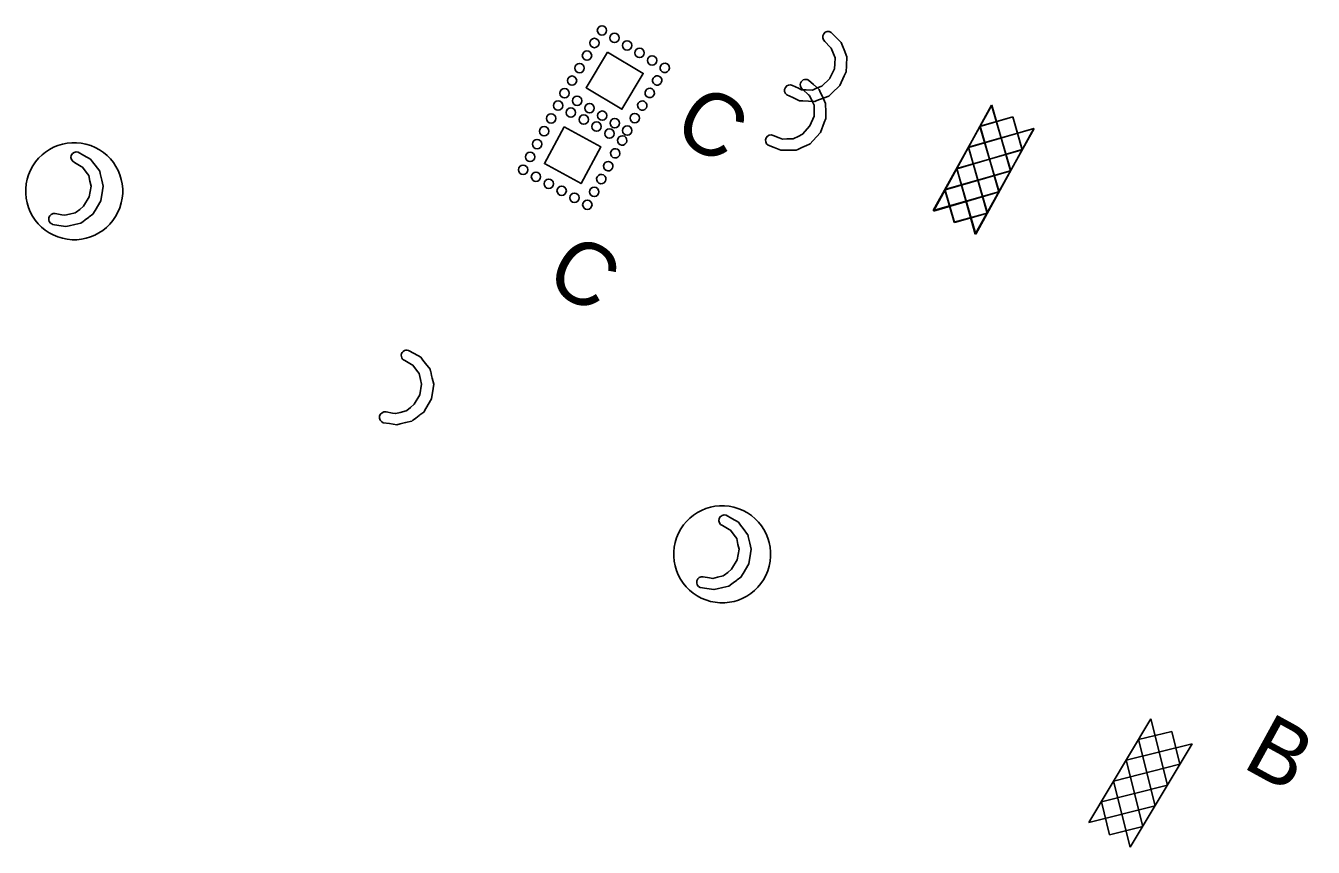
# Model space of a CAD drawing. Extents: x 2283629 to 2286552, y 529718 to 531440.
# Drawn here: x 2284496.6 to 2284805.1, y 530384.9 to 530581.6 of the extents above; entities that cross this region are included whole.
import ezdxf

# ---------------------------------------------------------------- set-up
doc = ezdxf.new("R2010")
doc.units = 0
for name, color, linetype in [('Draft_Corridor_Graphics_Final', 7, 'Continuous'), ('P_NCDOT_Terrain_Exterior', 7, 'Continuous'), ('P_NCDOT_Terrain_Model_Triangles', 7, 'Continuous'), ('P_NCDOT_Terrain_Triangle_Vertices', 7, 'Continuous'), ('P_NCDOT_Terrain_Void', 7, 'Continuous'), ('P_RDY_TC_Pvmt_Asphalt_Base_Course_Wedge', 7, 'Continuous'), ('P_RDY_TC_Pvmt_Asphalt_Intermediate_Course', 7, 'Continuous'), ('P_RDY_TC_Pvmt_Asphalt_Surface_Course', 7, 'Continuous'), ('P_RDY_TL_Paved_Shoulder_Sub', 7, 'Continuous'), ('P_RDY_TL_Sidewalk', 7, 'Continuous')]:
    doc.layers.add(name, color=color, linetype=linetype)

msp = doc.modelspace()

# ---------------------------------------------------------------- linework, layer by layer
at = {"layer": 'Draft_Corridor_Graphics_Final'}
for p, q in [((2284684.14, 530565.09), (2284684.38, 530564.86)), ((2284684.47, 530557.6), (2284684.46, 530557.59)), ((2284680.63, 530554.62), (2284680.41, 530554.52)), ((2284682.69, 530555.63), (2284681.62, 530555.11))]:
    msp.add_line(p, q, dxfattribs=at)
for points in [[(2284674.45, 530552.98), (2284675.89, 530552.42), (2284677.53, 530551.79), (2284678.34, 530551.8), (2284679.69, 530551.81), (2284681.2, 530551.83), (2284681.2, 530551.83), (2284681.54, 530551.99), (2284681.69, 530552.06), (2284682.36, 530552.36), (2284683.23, 530552.75), (2284683.45, 530552.85), (2284684.48, 530553.32), (2284685.18, 530554.07), (2284686.98, 530556.01), (2284686.98, 530556.02), (2284687.91, 530558.39), (2284688.29, 530559.36), (2284688.26, 530560.83), (2284688.25, 530561.49), (2284688.23, 530562.45), (2284688.23, 530562.53), (2284688.22, 530562.97), (2284688.22, 530563.01), (2284687.45, 530564.63), (2284687.02, 530565.54), (2284686.66, 530566.3), (2284685.31, 530567.51), (2284684.15, 530568.56)], [(2284682.77, 530566.36), (2284684.14, 530565.09), (2284684.38, 530564.86), (2284685.01, 530563.52), (2284685.45, 530562.59), (2284685.44, 530561.15), (2284685.44, 530559.94), (2284684.47, 530557.6), (2284684.46, 530557.59), (2284682.69, 530555.63), (2284681.62, 530555.11), (2284680.63, 530554.62), (2284680.41, 530554.52), (2284678.96, 530554.49), (2284677.86, 530554.46), (2284677.13, 530554.75), (2284675.68, 530555.33), (2284675.68, 530555.33)]]:
    msp.add_lwpolyline(points, dxfattribs=at)
for centre, radius, start in [((2284683.46, 530567.46), 1.3, 57.9198), ((2284675.16, 530554.11), 1.33, 66.8072)]:
    msp.add_arc(centre, radius, start, 237.9198, dxfattribs=at)
at = {"layer": 'P_NCDOT_Terrain_Exterior'}
for p, q in [((2284766.16, 530415.58), (2284751.29, 530390.79)), ((2284770.12, 530399.73), (2284766.16, 530415.58)), ((2284763.2, 530410.64), (2284771.14, 530412.6)), ((2284773.09, 530404.77), (2284771.14, 530412.6)), ((2284760.22, 530405.67), (2284776.06, 530409.64)), ((2284776.06, 530409.64), (2284761.2, 530384.85)), ((2284767.14, 530394.76), (2284763.2, 530410.64)), ((2284764.19, 530389.82), (2284760.22, 530405.67)), ((2284757.23, 530400.7), (2284773.1, 530404.71)), ((2284754.28, 530395.76), (2284770.12, 530399.73)), ((2284761.2, 530384.85), (2284757.23, 530400.7)), ((2284751.29, 530390.79), (2284767.14, 530394.76)), ((2284756.26, 530387.8), (2284754.28, 530395.76)), ((2284756.26, 530387.8), (2284764.19, 530389.82))]:
    msp.add_line(p, q, dxfattribs=at)
at = {"layer": 'P_NCDOT_Terrain_Model_Triangles'}
for p, q in [((2284689.35, 530576.51), (2284689.58, 530576.27)), ((2284685.2, 530566.29), (2284684.98, 530566.2)), ((2284687.32, 530567.17), (2284686.22, 530566.71)), ((2284689.21, 530569.01), (2284689.21, 530569))]:
    msp.add_line(p, q, dxfattribs=at)
for points in [[(2284678.93, 530565.03), (2284680.34, 530564.38), (2284681.93, 530563.65), (2284682.74, 530563.61), (2284684.08, 530563.54), (2284685.59, 530563.46), (2284685.6, 530563.47), (2284685.94, 530563.6), (2284686.1, 530563.66), (2284686.79, 530563.92), (2284687.68, 530564.26), (2284687.91, 530564.34), (2284688.96, 530564.75), (2284689.71, 530565.46), (2284691.62, 530567.27), (2284691.63, 530567.28), (2284692.7, 530569.59), (2284693.14, 530570.54), (2284693.2, 530572), (2284693.23, 530572.67), (2284693.27, 530573.62), (2284693.28, 530573.7), (2284693.29, 530574.14), (2284693.3, 530574.18), (2284692.63, 530575.85), (2284692.26, 530576.79), (2284691.94, 530577.56), (2284690.67, 530578.86), (2284689.58, 530579.97)], [(2284688.07, 530577.86), (2284689.35, 530576.51), (2284689.58, 530576.27), (2284690.12, 530574.9), (2284690.5, 530573.94), (2284690.41, 530572.5), (2284690.33, 530571.3), (2284689.21, 530569.01), (2284689.21, 530569), (2284687.32, 530567.17), (2284686.22, 530566.71), (2284685.2, 530566.29), (2284684.98, 530566.2), (2284683.53, 530566.25), (2284682.43, 530566.29), (2284681.71, 530566.63), (2284680.31, 530567.3), (2284680.31, 530567.3)]]:
    msp.add_lwpolyline(points, dxfattribs=at)
for centre, radius, start in [((2284688.82, 530578.92), 1.3, 54.3604), ((2284679.71, 530566.11), 1.33, 63.2478)]:
    msp.add_arc(centre, radius, start, 234.3604, dxfattribs=at)
at = {"layer": 'P_NCDOT_Terrain_Triangle_Vertices'}
for p, q in [((2284509.87, 530547.92), (2284508.27, 530548.87)), ((2284509.87, 530547.92), (2284510.15, 530547.75)), ((2284511.05, 530546.57), (2284510.15, 530547.75)), ((2284511.67, 530545.75), (2284511.05, 530546.57)), ((2284511.97, 530544.34), (2284511.67, 530545.75)), ((2284511.77, 530540.66), (2284512.22, 530543.16)), ((2284512.22, 530543.16), (2284511.97, 530544.34)), ((2284510.45, 530538.37), (2284509.52, 530537.63)), ((2284510.45, 530538.37), (2284511.77, 530540.65)), ((2284511.77, 530540.66), (2284511.77, 530540.65)), ((2284503.67, 530536.6), (2284505.2, 530536.33)), ((2284505.2, 530536.33), (2284505.98, 530536.2)), ((2284505.98, 530536.2), (2284507.05, 530536.46)), ((2284507.05, 530536.46), (2284508.46, 530536.8)), ((2284508.64, 530536.95), (2284508.46, 530536.8)), ((2284508.64, 530536.95), (2284509.52, 530537.63)), ((2284665.11, 530460.96), (2284663.51, 530461.91)), ((2284665.11, 530460.96), (2284665.4, 530460.79)), ((2284666.29, 530459.62), (2284665.4, 530460.79)), ((2284666.92, 530458.8), (2284666.29, 530459.62)), ((2284667.22, 530457.39), (2284666.92, 530458.8)), ((2284667.01, 530453.71), (2284667.47, 530456.21)), ((2284667.47, 530456.21), (2284667.22, 530457.39)), ((2284665.7, 530451.42), (2284667.01, 530453.7)), ((2284667.01, 530453.71), (2284667.01, 530453.7)), ((2284658.91, 530449.64), (2284660.44, 530449.38)), ((2284660.44, 530449.38), (2284661.22, 530449.25)), ((2284661.22, 530449.25), (2284662.29, 530449.51)), ((2284662.29, 530449.51), (2284663.7, 530449.85)), ((2284663.89, 530449.99), (2284663.7, 530449.85)), ((2284663.89, 530449.99), (2284664.76, 530450.68)), ((2284665.7, 530451.42), (2284664.76, 530450.68))]:
    msp.add_line(p, q, dxfattribs=at)
for points in [[(2284509.15, 530551.31), (2284510.5, 530550.53), (2284512.08, 530549.63), (2284512.59, 530548.97), (2284513.2, 530548.17), (2284514.3, 530546.75), (2284514.31, 530546.71), (2284514.41, 530546.28), (2284514.43, 530546.2), (2284514.65, 530545.27), (2284514.8, 530544.62), (2284515.13, 530543.2), (2284514.97, 530542.17), (2284514.56, 530539.65), (2284514.56, 530539.64), (2284513.21, 530537.37), (2284512.69, 530536.49), (2284511.78, 530535.81), (2284511.59, 530535.67), (2284510.82, 530535.1), (2284510.23, 530534.66), (2284510.09, 530534.56), (2284509.8, 530534.34), (2284509.79, 530534.34), (2284508.32, 530534), (2284507.01, 530533.7), (2284506.22, 530533.52), (2284504.48, 530533.79), (2284502.96, 530534.03)], [(2284664.39, 530464.35), (2284665.75, 530463.58), (2284667.32, 530462.68), (2284667.83, 530462.02), (2284668.45, 530461.21), (2284669.54, 530459.79), (2284669.55, 530459.75), (2284669.65, 530459.32), (2284669.67, 530459.25), (2284669.89, 530458.32), (2284670.04, 530457.67), (2284670.38, 530456.24), (2284670.21, 530455.21), (2284669.81, 530452.7), (2284669.8, 530452.69), (2284668.46, 530450.42), (2284667.93, 530449.53), (2284667.02, 530448.86), (2284666.83, 530448.72), (2284666.06, 530448.14), (2284665.47, 530447.71), (2284665.34, 530447.61), (2284665.04, 530447.39), (2284665.03, 530447.38), (2284663.56, 530447.05), (2284662.25, 530446.75), (2284661.46, 530446.57), (2284659.73, 530446.84), (2284658.2, 530447.08)]]:
    msp.add_lwpolyline(points, dxfattribs=at)
for centre, radius, start, end in [((2284508.2, 530541.97), 11.62, 70.1109, 160.1109), ((2284508.71, 530550.09), 1.3, 70.1109, 250.1109), ((2284508.2, 530541.97), 11.62, 340.1109, 70.1109), ((2284508.2, 530541.97), 11.62, 160.1109, 250.1109), ((2284503.41, 530535.29), 1.33, 78.9982, 250.1109), ((2284508.2, 530541.97), 11.62, 250.1109, 340.1109), ((2284663.44, 530455.01), 11.62, 70.1109, 160.1109), ((2284663.95, 530463.13), 1.3, 70.1109, 250.1109), ((2284663.44, 530455.01), 11.62, 340.1109, 70.1109), ((2284663.44, 530455.01), 11.62, 160.1109, 250.1109), ((2284658.65, 530448.33), 1.33, 78.9982, 250.1109), ((2284663.44, 530455.01), 11.62, 250.1109, 340.1109)]:
    msp.add_arc(centre, radius, start, end, dxfattribs=at)
at = {"layer": 'P_NCDOT_Terrain_Void'}
for p, q in [((2284714, 530537.34), (2284728.07, 530562.58)), ((2284728.07, 530562.58), (2284732.53, 530546.87)), ((2284738.16, 530556.96), (2284722.45, 530552.49)), ((2284724.09, 530531.72), (2284738.16, 530556.96)), ((2284733.1, 530559.79), (2284725.24, 530557.52)), ((2284725.24, 530557.52), (2284729.71, 530541.8)), ((2284733.1, 530559.79), (2284735.33, 530551.89)), ((2284735.33, 530551.89), (2284719.62, 530547.43)), ((2284722.45, 530552.49), (2284726.89, 530536.74)), ((2284732.53, 530546.87), (2284716.8, 530542.36)), ((2284719.62, 530547.43), (2284724.09, 530531.72)), ((2284729.71, 530541.8), (2284714, 530537.34)), ((2284716.82, 530542.29), (2284719.01, 530534.53)), ((2284726.89, 530536.74), (2284719.01, 530534.53))]:
    msp.add_line(p, q, dxfattribs=at)
at = {"layer": 'P_RDY_TC_Pvmt_Asphalt_Base_Course_Wedge'}
for p, q in [((2284589.03, 530500.47), (2284589.32, 530500.3)), ((2284590.98, 530493.22), (2284590.98, 530493.21)), ((2284587.88, 530489.49), (2284587.7, 530489.34)), ((2284589.68, 530490.93), (2284588.75, 530490.18))]:
    msp.add_line(p, q, dxfattribs=at)
for points in [[(2284582.21, 530486.53), (2284583.75, 530486.31), (2284585.48, 530486.05), (2284586.27, 530486.23), (2284587.58, 530486.54), (2284589.05, 530486.89), (2284589.06, 530486.89), (2284589.35, 530487.11), (2284589.49, 530487.22), (2284590.07, 530487.65), (2284590.84, 530488.23), (2284591.03, 530488.38), (2284591.93, 530489.06), (2284592.45, 530489.95), (2284593.78, 530492.22), (2284593.78, 530492.23), (2284594.17, 530494.75), (2284594.33, 530495.78), (2284593.98, 530497.21), (2284593.83, 530497.85), (2284593.6, 530498.78), (2284593.58, 530498.86), (2284593.48, 530499.29), (2284593.47, 530499.33), (2284592.36, 530500.74), (2284591.74, 530501.54), (2284591.23, 530502.2), (2284589.65, 530503.09), (2284588.29, 530503.85)], [(2284587.42, 530501.41), (2284589.03, 530500.47), (2284589.32, 530500.3), (2284590.22, 530499.13), (2284590.85, 530498.32), (2284591.16, 530496.9), (2284591.42, 530495.73), (2284590.98, 530493.22), (2284590.98, 530493.21), (2284589.68, 530490.93), (2284588.75, 530490.18), (2284587.88, 530489.49), (2284587.7, 530489.34), (2284586.29, 530488.99), (2284585.22, 530488.72), (2284584.44, 530488.85), (2284582.91, 530489.1), (2284582.91, 530489.1)]]:
    msp.add_lwpolyline(points, dxfattribs=at)
for centre, radius, start in [((2284587.85, 530502.63), 1.3, 70.514), ((2284582.66, 530487.79), 1.33, 79.4013)]:
    msp.add_arc(centre, radius, start, 250.514, dxfattribs=at)
at = {"layer": 'P_RDY_TC_Pvmt_Asphalt_Intermediate_Course'}
for p, q in [((2284650.6, 530570.89), (2284650.66, 530570.98)), ((2284648.81, 530567.89), (2284648.86, 530567.97)), ((2284647.02, 530564.89), (2284647.06, 530564.96)), ((2284645.23, 530561.89), (2284645.27, 530561.95)), ((2284640.44, 530553.53), (2284640.5, 530553.63)), ((2284638.78, 530550.46), (2284638.82, 530550.55)), ((2284637.11, 530547.39), (2284637.15, 530547.47)), ((2284635.44, 530544.33), (2284635.47, 530544.39))]:
    msp.add_line(p, q, dxfattribs=at)
for points in [[(2284635.93, 530575.31), (2284644.52, 530570.19), (2284639.4, 530561.6), (2284630.82, 530566.74)], [(2284625.61, 530557.37), (2284634.4, 530552.6), (2284629.62, 530543.81), (2284620.84, 530548.59)]]:
    msp.add_lwpolyline(points, close=True, dxfattribs=at)
for centre in [(2284634.64, 530580.48), (2284632.84, 530577.47), (2284637.64, 530578.68), (2284631.05, 530574.46), (2284640.65, 530576.89), (2284643.65, 530575.1), (2284629.26, 530571.46), (2284646.66, 530573.3), (2284627.46, 530568.45), (2284625.67, 530565.45), (2284624.11, 530562.48), (2284628.68, 530563.65), (2284631.68, 530561.86), (2284622.44, 530559.4), (2284627.18, 530560.8), (2284630.26, 530559.13), (2284634.69, 530560.07), (2284642.49, 530559.49), (2284620.77, 530556.33), (2284633.34, 530557.46), (2284636.41, 530555.79), (2284637.69, 530558.27), (2284640.7, 530556.48), (2284619.1, 530553.25), (2284617.42, 530550.18), (2284615.75, 530547.1), (2284618.83, 530545.43), (2284621.9, 530543.76), (2284624.98, 530542.09), (2284628.05, 530540.41), (2284632.8, 530541.82), (2284631.13, 530538.74)]:
    msp.add_circle(centre, 1.12, dxfattribs=at)
for centre, start, end in [((2284649.67, 530571.51), 331.994, 326.3782), ((2284647.87, 530568.5), 331.6976, 326.6747), ((2284646.08, 530565.5), 331.361, 327.0112), ((2284644.29, 530562.49), 330.9619, 327.4103), ((2284639.49, 530554.12), 334.2864, 328.6706), ((2284637.81, 530551.04), 333.9899, 328.967), ((2284636.14, 530547.97), 333.6534, 329.3036), ((2284634.47, 530544.89), 333.2543, 329.7027)]:
    msp.add_arc(centre, 1.12, start, end, dxfattribs=at)
at = {"layer": 'P_RDY_TL_Sidewalk'}
for p, q in [((2284714.1, 530537.23), (2284728, 530562.57)), ((2284728, 530562.57), (2284732.57, 530546.89)), ((2284738.13, 530557.01), (2284722.45, 530552.44)), ((2284724.22, 530531.68), (2284738.13, 530557.01)), ((2284733.05, 530559.81), (2284725.2, 530557.49)), ((2284725.2, 530557.49), (2284729.78, 530541.8)), ((2284733.05, 530559.81), (2284735.34, 530551.93)), ((2284735.34, 530551.93), (2284719.66, 530547.36)), ((2284722.45, 530552.44), (2284726.99, 530536.72)), ((2284732.57, 530546.89), (2284716.87, 530542.27)), ((2284719.66, 530547.36), (2284724.22, 530531.68)), ((2284729.78, 530541.8), (2284714.1, 530537.23)), ((2284716.89, 530542.21), (2284719.13, 530534.46)), ((2284726.99, 530536.72), (2284719.13, 530534.46))]:
    msp.add_line(p, q, dxfattribs=at)

# ---------------------------------------------------------------- texts
at = {"layer": 'P_RDY_TC_Pvmt_Asphalt_Surface_Course'}
for p in [(2284650.99, 530555.43), (2284620.38, 530519.67)]:
    msp.add_text('C', height=15, rotation=329.1861, dxfattribs=at).set_placement(p)
at = {"layer": 'P_RDY_TL_Paved_Shoulder_Sub'}
msp.add_text('B', height=15, rotation=331.2423, dxfattribs=at).set_placement((2284787.74, 530404.17))

doc.saveas('drawing.dxf')
